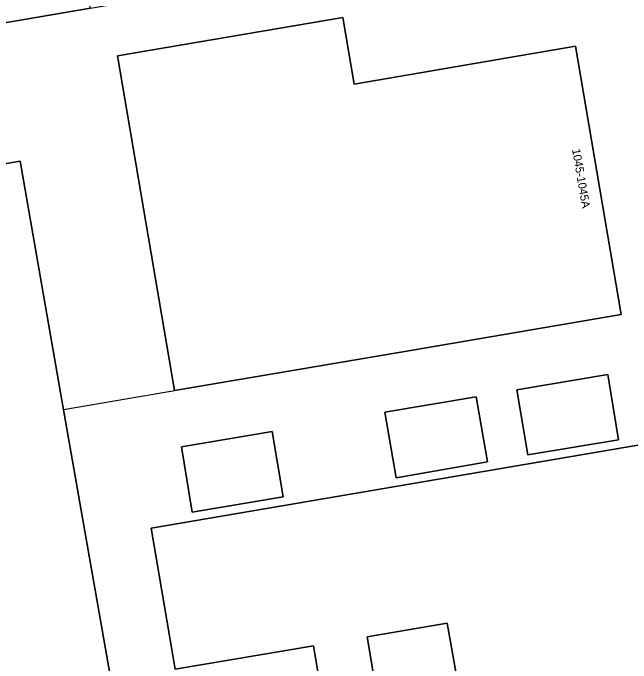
# Model space of a CAD drawing. Extents: x 154324 to 155744, y 382937 to 384188.
# Drawn here: x 154943.2 to 155018, y 383617.3 to 383695.9 of the extents above; entities that cross this region are included whole.
import ezdxf

# ---------------------------------------------------------------- set-up
doc = ezdxf.new("R2010")
doc.units = 0
for name, color, linetype in [('IMGEO_Erf', 7, 'Continuous'), ('IMGEO_Grasland_agrarisch', 7, 'Continuous'), ('IMGEO_Muur', 7, 'Continuous'), ('IMGEO_Pand', 7, 'Continuous'), ('IMGEO_Pand_nummerreeks', 7, 'Continuous')]:
    doc.layers.add(name, color=color, linetype=linetype)

msp = doc.modelspace()

# ---------------------------------------------------------------- linework, layer by layer
at = {"layer": 'IMGEO_Erf'}
msp.add_lwpolyline([(154925.991, 383785.242), (154933.724, 383739.787), (154944.892, 383741.692), (154944.883, 383741.744), (155001.211, 383751.343), (155008.926, 383706.026), (154952.606, 383696.427), (154952.596, 383696.484), (154892.427, 383686.211), (154895.235, 383669.681), (154944.096, 383677.972), (154949.335, 383647.913), (154982.713, 383457.883)], dxfattribs=at)
for points in [[(154989.897, 383654.816), (154962.764, 383650.229), (154955.863, 383690.706), (154983.103, 383695.375), (154984.482, 383687.305), (155011.244, 383691.878), (155016.791, 383659.412)], [(155004.172, 383650.316), (155015.152, 383652.183), (155016.468, 383644.26), (155005.482, 383642.434)], [(154989.589, 383639.683), (154988.209, 383647.601), (154999.229, 383649.475), (155000.602, 383641.603)], [(154964.911, 383635.527), (154963.6, 383643.417), (154974.59, 383645.286), (154975.908, 383637.355)], [(154968.856, 383582.036), (154965.968, 383599.167), (154982.677, 383602.011), (154981.855, 383606.811), (154988.34, 383607.922), (154989.336, 383602.109), (154998.998, 383603.747), (154995.748, 383622.105), (154986.045, 383620.456), (154986.86, 383615.621), (154980.368, 383614.527), (154979.569, 383619.356), (154962.835, 383616.513), (154959.94, 383633.571), (155019.3, 383643.685), (155023.472, 383619.228), (155022.401, 383619.041), (155023.514, 383612.464), (155024.589, 383612.647), (155025.346, 383608.213), (155028.11, 383592.025)]]:
    msp.add_lwpolyline(points, close=True, dxfattribs=at)
at = {"layer": 'IMGEO_Grasland_agrarisch'}
msp.add_lwpolyline([(154982.713, 383457.883), (154949.335, 383647.913), (154944.096, 383677.972), (154895.235, 383669.681), (154886.005, 383668.098), (154936.688, 383370.604)], dxfattribs=at)
at = {"layer": 'IMGEO_Muur'}
msp.add_lwpolyline([(154989.897, 383654.816), (154949.335, 383647.913)], dxfattribs=at)
at = {"layer": 'IMGEO_Pand'}
for points in [[(154944.892, 383741.692), (154933.724, 383739.787), (154904.981, 383734.884), (154905.008, 383734.726), (154907.633, 383719.324), (154885.53, 383715.542), (154890.574, 383685.895), (154892.427, 383686.211), (154952.596, 383696.484)], [(155011.244, 383691.878), (154984.482, 383687.305), (154983.103, 383695.375), (154955.863, 383690.706), (154962.764, 383650.229), (154989.897, 383654.816), (155016.791, 383659.412)], [(155015.152, 383652.183), (155004.172, 383650.316), (155005.482, 383642.434), (155016.468, 383644.26)], [(154999.229, 383649.475), (154988.209, 383647.601), (154989.589, 383639.683), (155000.602, 383641.603)], [(154974.59, 383645.286), (154963.6, 383643.417), (154964.911, 383635.527), (154975.908, 383637.355)], [(155022.401, 383619.041), (155023.472, 383619.228), (155019.3, 383643.685), (154959.94, 383633.571), (154962.835, 383616.513), (154979.569, 383619.356), (154980.368, 383614.527), (154986.86, 383615.621), (154986.045, 383620.456), (154995.748, 383622.105), (154998.998, 383603.747), (154989.336, 383602.109), (154988.34, 383607.922), (154981.855, 383606.811), (154982.677, 383602.011), (154965.968, 383599.167), (154968.856, 383582.036), (155028.11, 383592.025), (155025.346, 383608.213), (155024.589, 383612.647), (155023.514, 383612.464)]]:
    msp.add_lwpolyline(points, close=True, dxfattribs=at)

# ---------------------------------------------------------------- texts
at = {"layer": 'IMGEO_Pand_nummerreeks'}
msp.add_text('1045-1045A', height=1, rotation=279.69424, dxfattribs=at).set_placement((155010.84, 383679.4))

doc.saveas('drawing.dxf')
